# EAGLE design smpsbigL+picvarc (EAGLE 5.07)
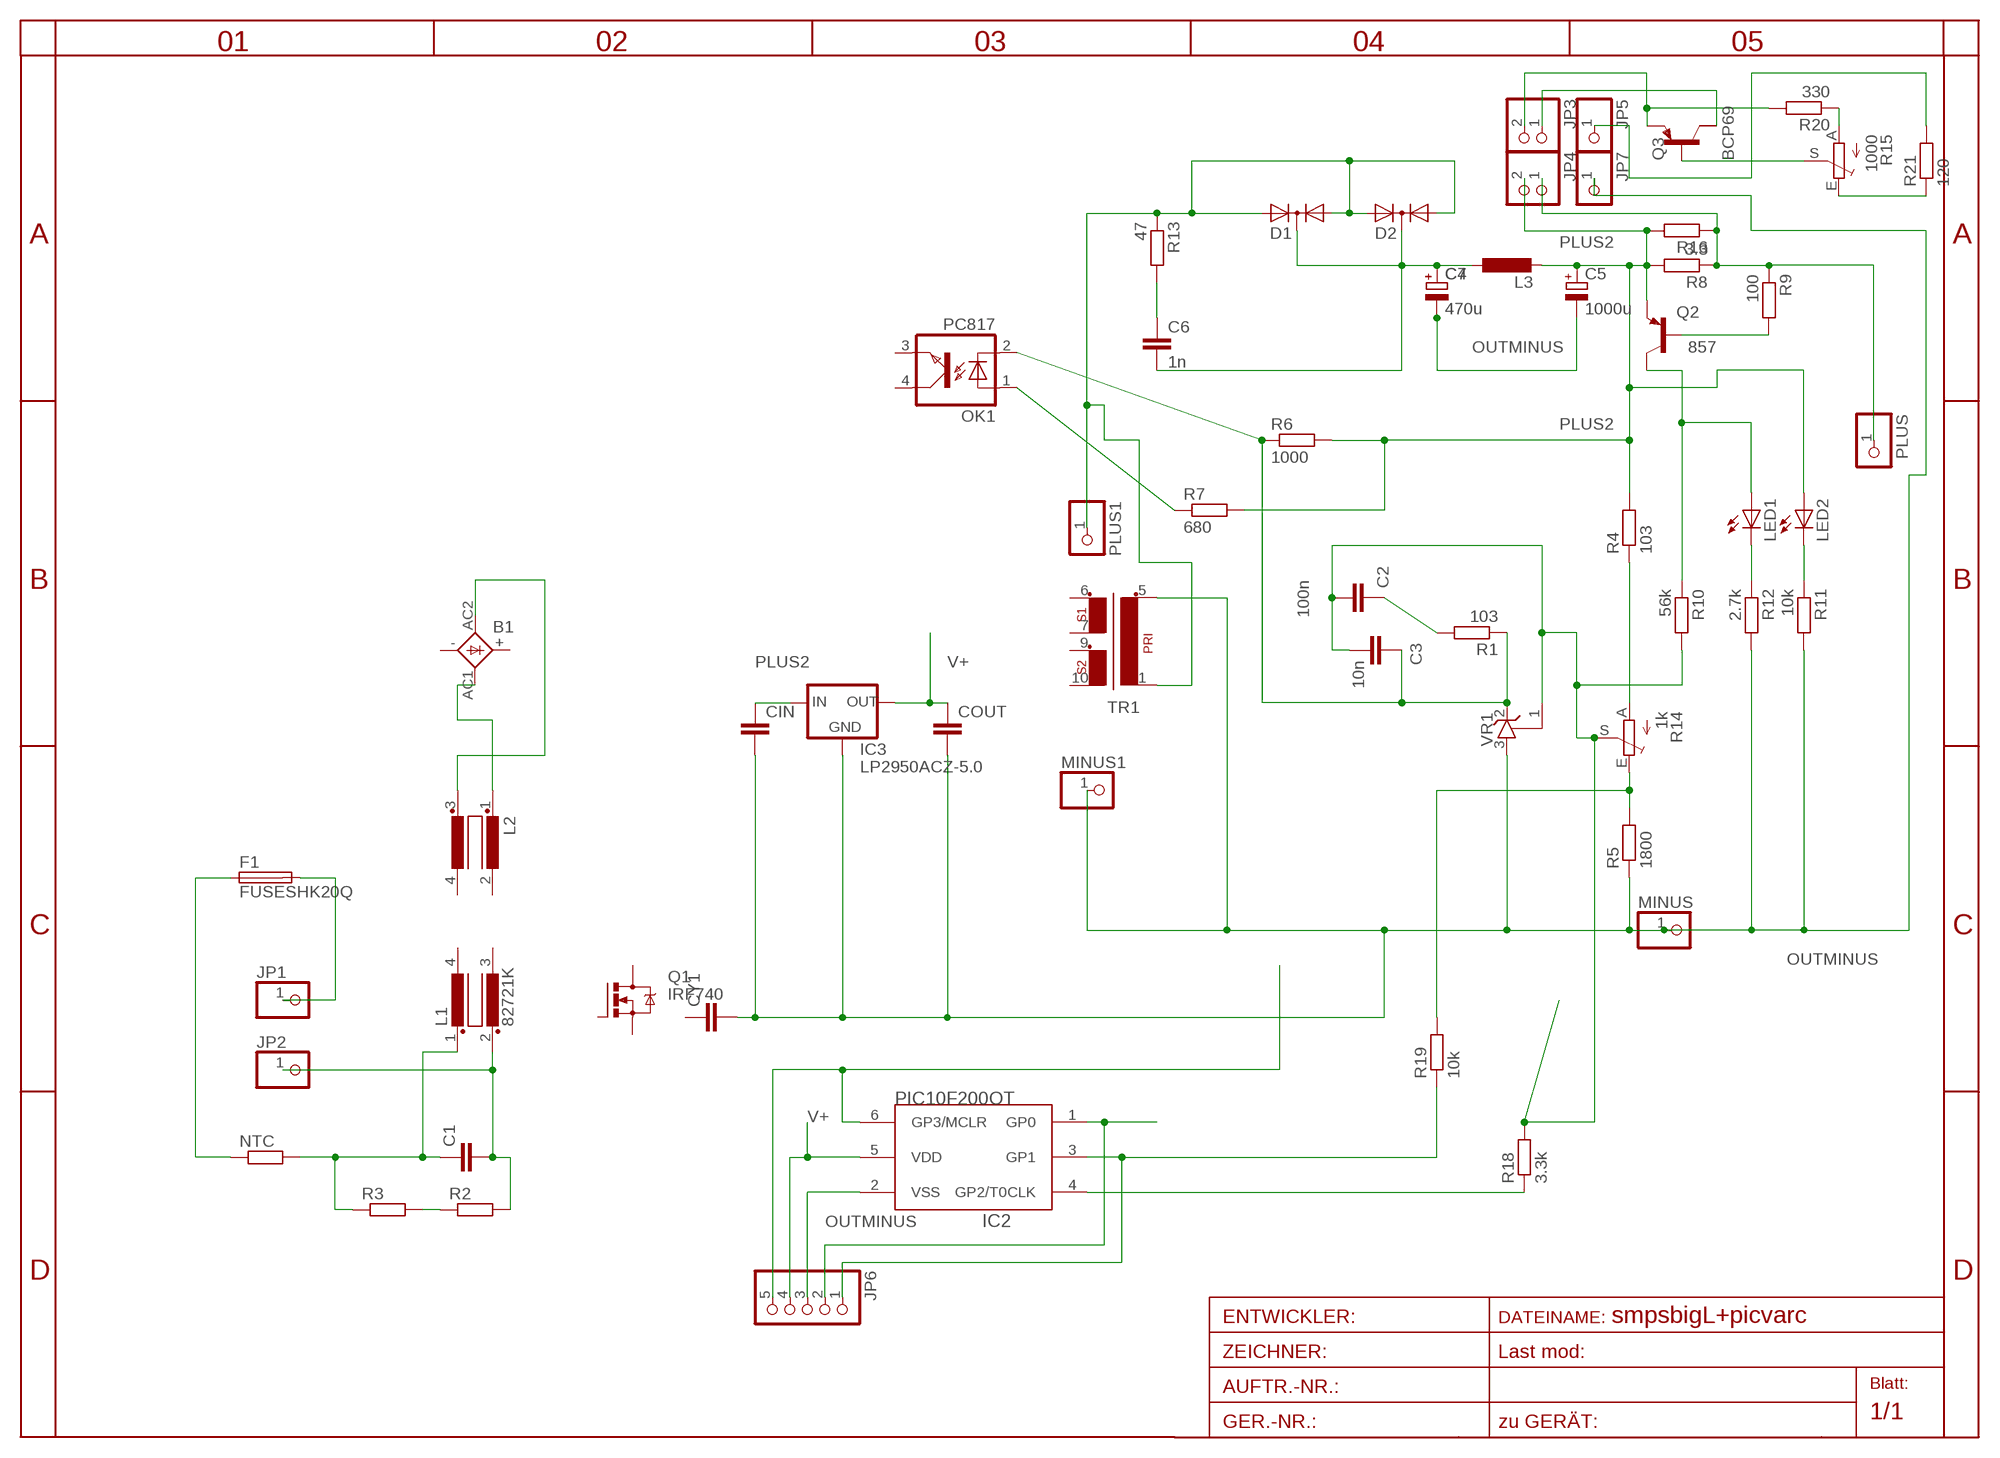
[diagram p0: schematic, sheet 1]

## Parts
B1  KBL  [KBL]
C1  C-EU150-084X183  [C150-084X183]
C2  100n  C-EUC0805  [C0805]
C3  10n  C-EUC0805  [C0805]
C4  CPOL-EUE5-8.5  [E5-8,5]
C5  1000u  CPOL-EUE5-8.5  [E5-8,5]
C6  1n  C-EUC0805  [C0805]
C7  470u  CPOL-EUE2.5-7  [E2,5-7]
CIN  C-EUC1206  [C1206]
COUT  C-EUC1206  [C1206]
CY1  C-EU075-063X106  [C075-063X106]
D1  DIODE-2AC|CAIW220V  [IW220ABS]
D2  DIODE-2AC|CAIW220V  [IW220ABS]
F1  FUSESHK20Q  [SHK20Q]
IC2  PIC10F200OT  [SOT23-6]
IC3  LP2950ACZ-5.0  [TO92]
JP1  PINHD-1X12MM2  [1X2MM2]
JP2  PINHD-1X12MM2  [1X2MM2]
JP3  PINHD-1X2STR  [1X02]
JP4  PINHD-1X2STR  [1X02]
JP5  PINHD-1X11X0.4  [1X01]
JP6  PINHD-1X5/90  [1X05/90]
JP7  PINHD-1X11X0.4  [1X01]
L1  82721K  [82721K]
L2  R1405VB1  [B1]
L3  L-EUOPEN6  [OPEN6_3]
LED1  LED3MM  [LED3MM]
LED2  LED3MM  [LED3MM]
MINUS  PINHD-1X12MM2  [1X2MM2]
MINUS1  PINHD-1X11X0.4  [1X01]
NTC  R-EU_0204/7  [0204/7]
OK1  PC817  [DIL04]
PLUS  PINHD-1X12MM2  [1X2MM2]
PLUS1  PINHD-1X11X0.4  [1X01]
Q1  IRF740  [TO220BV]
Q2  857  BC857ASMD  [SOT23-BEC]
Q3  BCP69  FZT753SMD  [SOT223]
R1  103  R-EU_R0805  [R0805]
R2  R-EU_R1206  [R1206]
R3  R-EU_R1206  [R1206]
R4  103  R-EU_R0805  [R0805]
R5  1800  R-EU_R0805  [R0805]
R6  1000  R-EU_R0805  [R0805]
R7  680  R-EU_R0805  [R0805]
R8  3.3  R-EU_R1210  [R1210]
R9  100  R-EU_0204/7  [0204/7]
R10  56k  R-EU_R0805  [R0805]
R11  10k  R-EU_R0805  [R0805]
R12  2.7k  R-EU_R0805  [R0805]
R13  47  R-EU_R1206  [R1206]
R14  1k  TRIM_EU-S64W  [S64W]
R15  1000  TRIM_EU-RAND160  [RANDL]
R16  R-EU_R2010  [R2010]
R18  3.3k  R-EU_R0805  [R0805]
R19  10k  R-EU_R0805  [R0805]
R20  330  R-EU_R0805  [R0805]
R21  120  R-EU_R0805  [R0805]
TR1  EE20-2  [EE30GREEN]
VR1  TL431CLPSOT23  [SOT23]

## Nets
A: R4.1 R14.A
C1: LED1.A Q2.C R10.1
CPLUS: C4.+ C6.2 C7.+ D1.C D2.C L3.1
E: R5.2 R14.E R19.2
N$1: C1.2 JP2.1 L1.2 R2.2
N$2: C1.1 L1.1 NTC.2 R3.1
N$3: F1.2A JP1.1
N$4: Q3.1(B) R15.S
N$5: R15.A R20.1
N$6: R2.1 R3.2
N$7: B1.AC2(AC1) L2.3
N$8: B1.AC1(AC2) L2.1
N$9: F1.1A NTC.1
N$10: R15.E R21.1
N$11: C3.1 OK1.2(C) R1.1 R6.1 VR1.2(C)
N$12: OK1.1(A) R7.1
N$13: C2.1 R1.2
N$14: JP3.2 Q3.3(E) R20.2
N$15: IC2.6(GP3/MCLR) JP6.5
N$16: Q2.B R9.2
N$17: IC2.1(GP0) JP6.2
N$18: IC2.3(GP1) JP6.1 R19.1
N$19: IC2.4(GP2/T0CLK) R18.1
N$20: JP3.1 Q3.2(C)
N$21: LED1.K(C) R12.1
N$22: JP5.1 R21.2
N$23: LED2.K(C) R11.1
N$27: C6.1 R13.2
OUTMINUS: C4.- C5.- C7.- CIN.2 COUT.2 CY1.2 IC2.2(VSS) IC3.2(GND) JP6.3 JP7.1 MINUS1.1 MINUS.1 R5.1 R11.2 R12.2 TR1.5 VR1.3(A)
OUTPLUS: JP4.1 PLUS.1 R8.1 R9.1 R16.1
PLUS2: C5.+ CIN.1 IC3.3(IN) JP4.2 L3.2 LED2.A Q2.E R4.2 R6.2 R7.2 R8.2 R16.2
S: C2.2 C3.2 R10.2 R14.S R18.2 VR1.1(R)
TOUT: D1.A1 D1.A2 D2.A1 D2.A2 PLUS1.1 R13.1 TR1.1
V+: COUT.1 IC2.5(VDD) IC3.1(OUT) JP6.4
Unconnected: B1.+ B1.- CY1.1 L1.3 L1.4 L2.2 L2.4 OK1.3(EMIT) OK1.4(COL) Q1.D Q1.G Q1.S Q3.4(C/) TR1.6 TR1.7 TR1.9 TR1.10

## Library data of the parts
B1 = rectifier:KBL: DIOTEC RECTIFIER
C1-C3 C6 CIN COUT CY1 = rcl:C-EU: CAPACITOR, European symbol
C4 C5 C7 = rcl:CPOL-EU: POLARIZED CAPACITOR, European symbol
D1 D2 = diode:DIODE-2AC|CA: Dual DIODE Anode-Cathode|Cathode-Anode
F1 = fuse:FUSE: Fuse
IC2 = microchip-5:PIC10F20*: uPC nW 0,25/0,5k Program Flash memory
IC3 = v-reg:LP2950?*: Source: http://cache.national.com/ds/LP/LP2950.pdf
JP1 JP2 JP5 JP7 MINUS MINUS1 PLUS PLUS1 = pinhead:PINHD-1X1: PIN HEADER
JP3 JP4 = pinhead:PINHD-1X2: PIN HEADER
JP6 = pinhead:PINHD-1X5: PIN HEADER
L1 = inductors:82721K: FILTER
L2 = inductor-nkl:R1405V: Übertrager (verlustarm) bis typ. 400kHz Power transformer (low loss) up to typ. 400kHz
L3 = rcl:L-EU: INDUCTOR, European symbol
LED1 LED2 = led:LED: LED
NTC R1-R13 R16 R18-R21 = rcl:R-EU_: RESISTOR, European symbol
OK1 = optocoupler:PC817: SHARP OPTO COUPLER
Q1 = transistor-power:IRF740: N-CHANNEL MOS FET
Q2 = transistor-pnp:BC857*: PNP Transistror
Q3 = transistor-pnp:FZT753SMD: PNP Transistor
R14 R15 = pot:TRIM_EU-: POTENTIOMETER
TR1 = trafo:EE20-2: TRANSFORMER 1 primary winding, 2 secondary windings ERA
VR1 = v-reg:TL431CLP: VOLTAGE REGULATOR

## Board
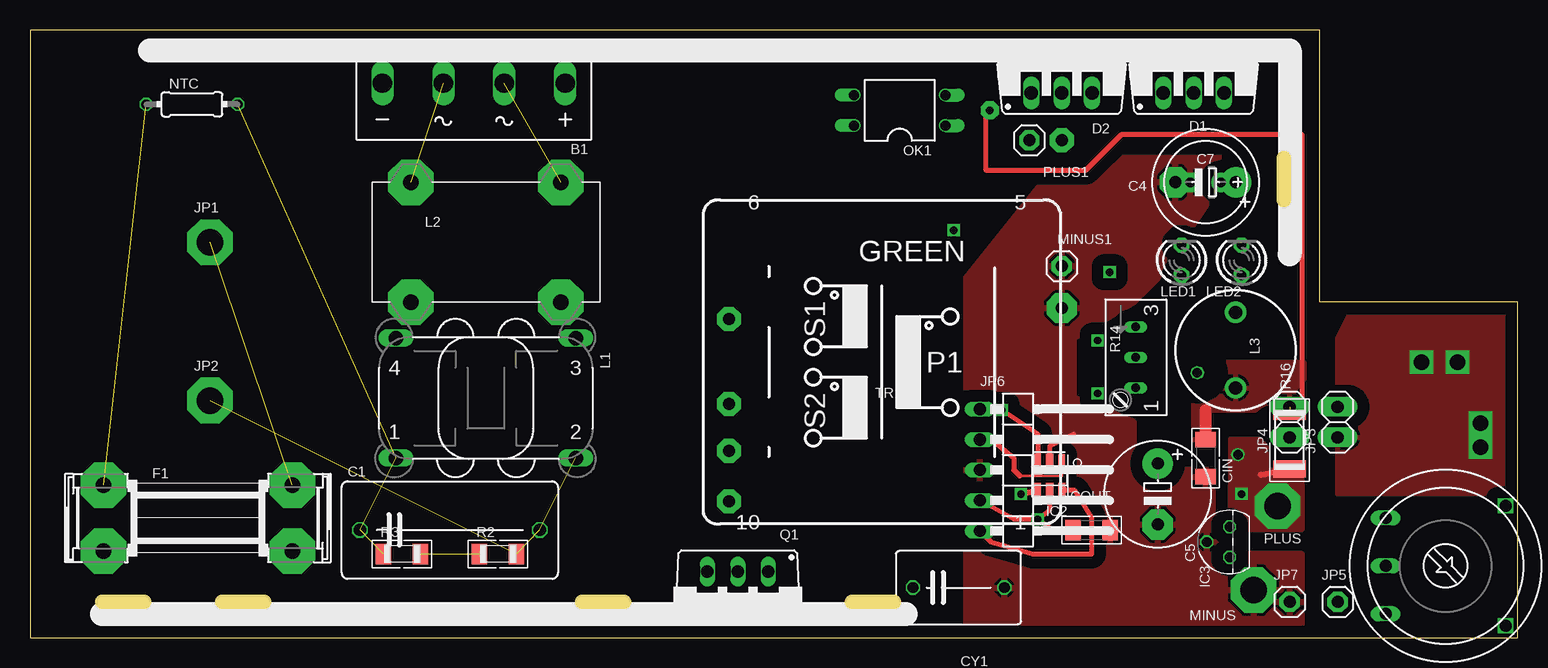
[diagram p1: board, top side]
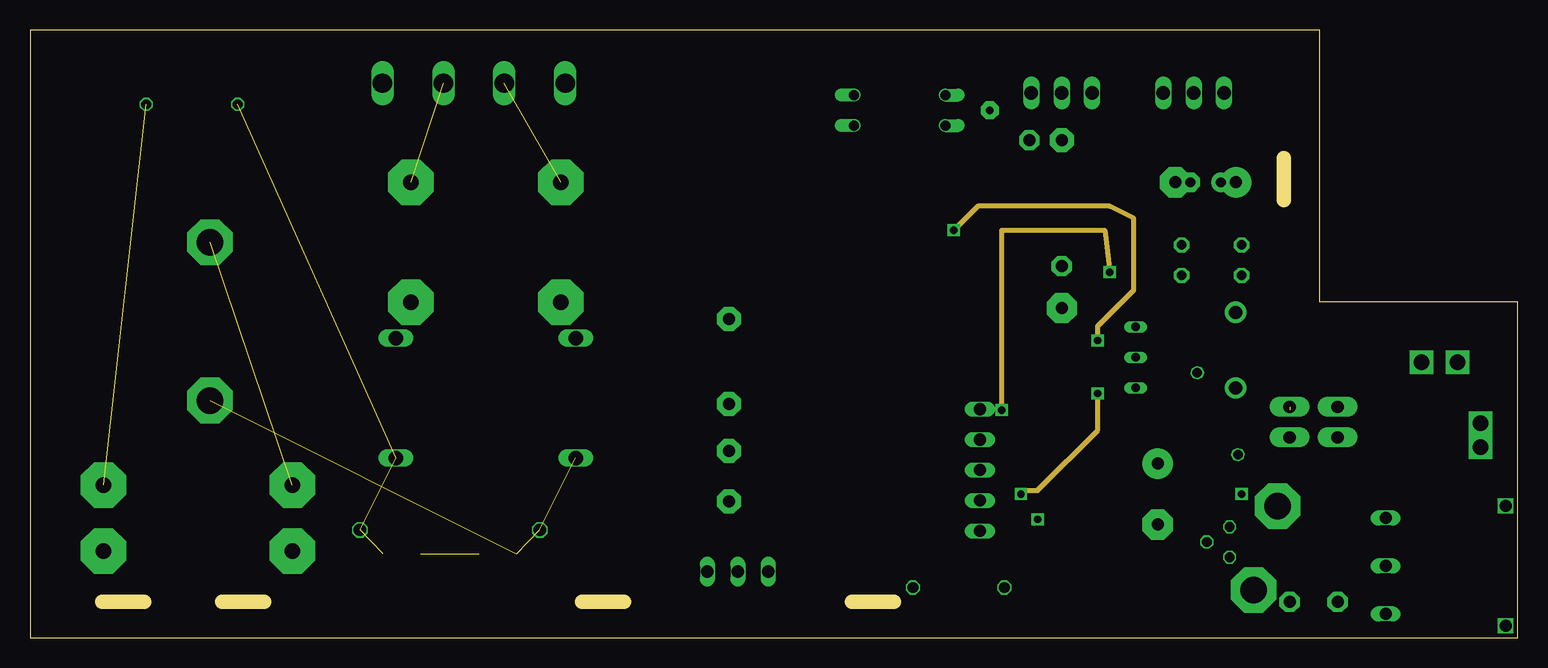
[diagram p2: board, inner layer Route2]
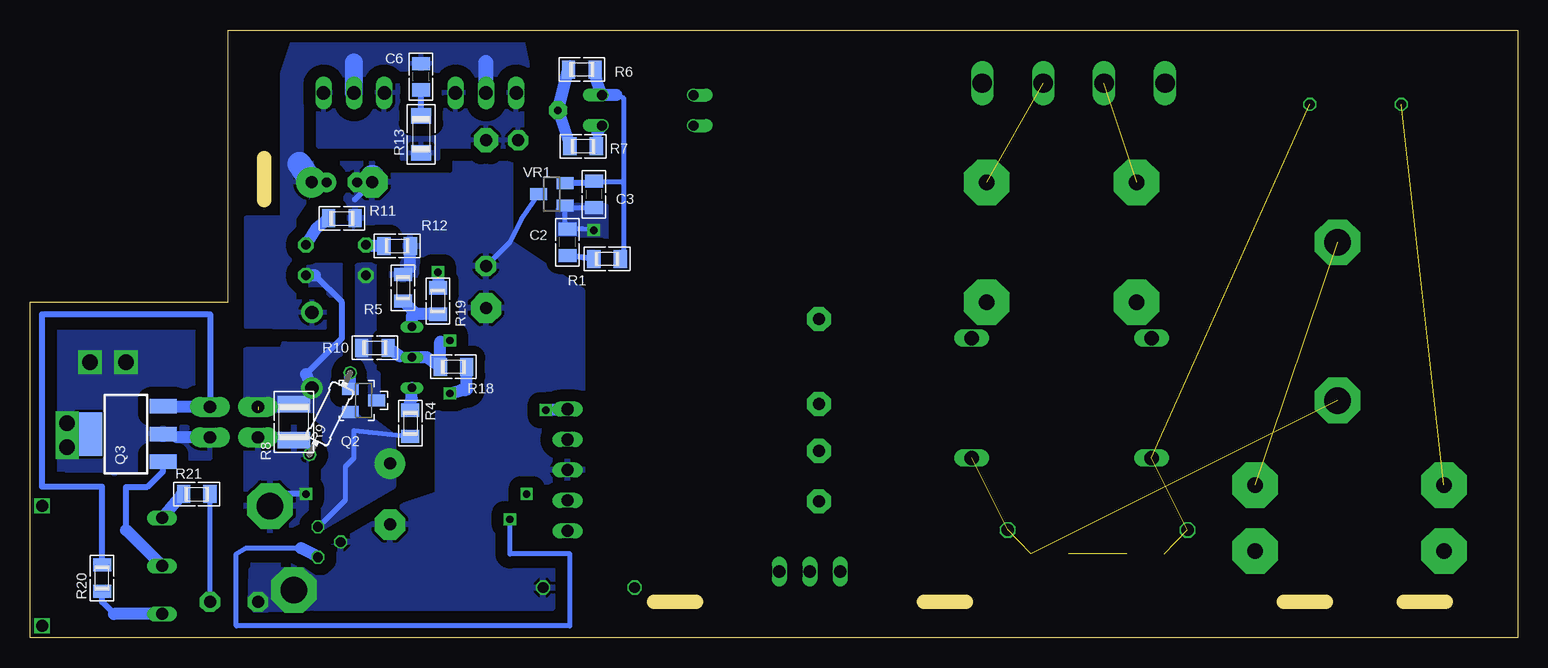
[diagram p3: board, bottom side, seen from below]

Size 124 x 50.7 mm. Coordinates in mm from the lower left corner, seen from the top.
Outline: 0,0 124,0 124,28 107.5,28 107.5,50.7 0,50.7 0,0
Copper layers (1*16): Top 0.035mm / dielectric 1.5mm / Bottom 0.035mm
Design rules "default *": minimum track width 10mil, minimum drill 20mil, track to track 8mil, track to pad 8mil, pad to pad 8mil, via to via 8mil, smd to smd 8mil, copper to edge 40mil, drill to drill 8mil, minimum pad ring 5mil, minimum via ring 8mil, stop-mask expansion 4mil, vias tented up to drill 0mil, thermal gap 10mil
Milling: 5 lines

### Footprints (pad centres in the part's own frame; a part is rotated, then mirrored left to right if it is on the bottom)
KBL = drill 1.6 long: + -7.62,-1.27; - 7.62,-1.27; AC1 2.54,-1.27; AC2 -2.54,-1.27
C150-084X183 = drill 1.016 octagon: 1 -7.493,0; 2 7.493,0
C0805 = smd 1.1 x 1.5: 1 -1.1,0; 2 1.1,0
E5-8,5 = drill 1 pad 2.54 round: + -2.54,0 | drill 1 pad 2.54 octagon: - 2.54,0
E2,5-7 = drill 0.813 pad 1.6 round: + -1.27,0 | drill 0.813 pad 1.6 octagon: - 1.27,0
C1206 = smd 1.3 x 1.7: 1 -1.55,0; 2 1.55,0
C075-063X106 = drill 0.914 octagon: 1 -3.81,0; 2 3.81,0
IW220ABS = drill 1.118 long: A1 -2.54,-2.54; A2 2.54,-2.54; C 0,-2.54
SHK20Q = drill 1.3 pad 3.81 octagon: 1A -7.874,2.75; 1B -7.874,-2.75; 2A 7.874,2.75; 2B 7.874,-2.75
SOT23-6 = smd 0.55 x 1.2: 1 -1.016,-1.2 | smd 0.6 x 1.27: 2 0,-1.2; 3 1.016,-1.2; 4 1.016,1.2; 5 0,1.2; 6 -1.016,1.2
TO92 = drill 0.813 octagon: 1 -1.27,0; 2 0,1.905; 3 1.27,0
1X2MM2 = drill 2.2 pad 3.81 octagon: 1 0,0
1X02 = drill 1.016 pad 1.676 long: 1 -1.27,0; 2 1.27,0
1X01 = drill 1 pad 1.676 octagon: 1 0,0
1X05/90 = drill 1.016 long: 1 -5.08,-3.81; 2 -2.54,-3.81; 3 0,-3.81; 4 2.54,-3.81; 5 5.08,-3.81
82721K = drill 1.194 long: 1 7.493,5.004; 2 -7.493,5.004; 3 -7.493,-5.004; 4 7.493,-5.004
B1 = drill 1.27 pad 3.81 octagon: 1 -6.25,5; 2 -6.25,-5; 3 6.25,5; 4 6.25,-5
OPEN6_3 = drill 1.1 pad 1.778 round: 1 -3.15,0; 2 3.15,0
LED3MM = drill 0.8 pad 1.27 octagon: A -1.27,0; K 1.27,0
0204/7 = drill 0.813 octagon: 1 -3.81,0; 2 3.81,0
DIL04 = drill 0.813 offset: 1 -1.27,-3.81; 2 1.27,-3.81; 3 1.27,3.81; 4 -1.27,3.81
TO220BV = drill 1.016 long: D 0,-2.54; G -2.54,-2.54; S 2.54,-2.54
SOT23-BEC = smd 1 x 1.4: B -0.95,-1.1; C 0,1.1; E 0.95,-1.1
SOT223 = smd 1.219 x 2.235: 1 -2.311,-3.099; 2 0,-3.099; 3 2.311,-3.099 | smd 3.6 x 2.2: 4 0,3.099
R0805 = smd 1.1 x 1.5: 1 -1.1,0; 2 1.1,0
R1206 = smd 1.3 x 1.7: 1 -1.55,0; 2 1.55,0
R1210 = smd 1.4 x 2.7: 1 -1.5,0; 2 1.5,0
S64W = drill 0.7 long: A 2.54,1.27; E -2.54,1.27; S 0,1.27
RANDL = drill 1 long: A -4,5; E 4,5; S 0,5 | drill 1 square: P$1 -5,-5; P$2 5,-5
R2010 = smd 1.4 x 2.7: 1 -2.4,0; 2 2.4,0
EE30GREEN = drill 1 pad 2 octagon: 1 15,18.5; 6 -12.75,3.6; 7 -12.75,-3.5; 9 -12.75,-7.4; 10 -12.75,-11.6 | drill 1 pad 2.5 octagon: 5 15,4.5
SOT23 = smd 1 x 1.4: 1 -0.95,-1.1; 2 0.95,-1.1; 3 0,1.1

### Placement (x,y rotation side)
B1  37,45 180 top
C1  35,9 0 top
C2  79.2,33 90 bottom
C3  77,37 270 bottom
C4  98,38 180 top
C5  94,12 270 top
C6  91.4,46.8 90 bottom
C7  98,38 180 top
CIN  98,15 270 top
COUT  88.5,9 0 top
CY1  77.4,4.2 0 top
D1  97,48 0 top
D2  86,48 0 top
F1  14,10 0 top
IC2  85,13.5 180 top
IC3  100,8 90 top
JP1  15,33 0 top
JP2  15,19.8 0 top
JP3  109,18 90 top
JP4  105,18 90 top
JP5  109,3 0 top
JP6  83,14 270 top
JP7  105,3 0 top
L1  38,20 180 top
L2  38,33 0 top
L3  100.5,24 270 top
LED1  96,31.5 90 top
LED2  101,31.5 90 top
MINUS  102,4 0 top
MINUS1  86,31 0 top
NTC  13.5,44.5 0 top
OK1  72.5,44 90 top
PLUS  104,11 0 top
PLUS1  83.3,41.5 0 top
Q1  59,3 180 top
Q2  96.2,19.8 270 bottom
Q3  116,17 90 bottom
R1  75.9,31.6 180 bottom
R2  39,7 0 top
R3  31,7 0 top
R4  92.3,17.9 270 bottom
R5  92.9,29.2 270 bottom
R6  78,47.4 180 bottom
R7  77.9,41 180 bottom
R8  102,18 90 bottom
R9  99,18.7 63.5 bottom
R10  95.25,24.2 0 bottom
R11  98,35 0 bottom
R12  93.4,32.7 0 bottom
R13  91.4,42 90 bottom
R14  90.9,23.4 270 top
R15  118,6 90 top
R16  105,16.5 90 top
R18  88.7,22.6 180 bottom
R19  90,28.1 270 bottom
R20  118,5 90 bottom
R21  110.1,12 0 bottom
TR1  71,23 0 top
VR1  80.5,37 90 bottom

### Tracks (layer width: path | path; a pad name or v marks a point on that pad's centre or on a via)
A
  Bottom 0.406: 92.3,19.7 92.17,19.93
  Bottom 1.016: R4.1 92.3,19.7 | 92.17,19.93 R14.A
C1
  pour Bottom (isolate 0.8, rank 3, no thermals): 95.3,31.2 96.7,31 96.7,19.9 95,20 95,22 95.3,22.2
CPLUS
  Bottom 1.27: D2.C 86,48
  Bottom 1.5: D1.C 97,48
  Bottom 2: C4.+ 101.54,39.54
  pour Bottom (isolate 1, rank 3): 83,50 102,50 103,47 103,35 106,35 106,26 99.4,25.9 99.4,28 102,28 102,31 102,35 100,38 101.1,45.8 82.1,45.8
E
  Bottom 0.406: 91.8,27 91.9,27.1 92.17,26.83
  Bottom 1.016: R19.2 91.8,27 | 91.9,27.1 R5.2 | 92.17,26.83 R14.E
N$1  (3 unrouted)
N$2  (3 unrouted)
N$3  (1 unrouted)
N$4
  Bottom 0.5: 116,9 116,12.59 114.2,12.6 112.9,13.9 Q3.1
  Bottom 1: R15.S 116,9
N$5
  Bottom 0.5: 117,2 118,3 R20.1
  Bottom 1: R15.A 117,2
N$6  (1 unrouted)
N$7  (1 unrouted)
N$8  (1 unrouted)
N$9  (1 unrouted)
N$10
  Bottom 0.406: R21.1 111.4,11.9
  Bottom 1: 111.4,11.9 R15.E
N$11
  Bottom 0.406: 77.15,37.95 C3.1 76.9,38 74.5,38 | 74.5,31.8 74.5,38 | 76.81,46.61 R6.1 | 75.13,45.27 74.5,45 74.5,38
  Bottom 0.5: 77.15,37.95 VR1.2 | R1.1 74.5,31.8
  Bottom 1: 76.81,46.61 OK1.2 75.13,45.27
N$12
  Bottom 0.5: R7.1 76.7,42.14
  Bottom 1: 76.7,42.14 OK1.1
N$13
  Bottom 0.5: R1.2 C2.1
N$14
  Bottom 0.406: 112.86,19.27 Q3.3
  Bottom 0.5: R20.2 118,12.6 123,12.6 123,27 109,27 JP3.2
  Bottom 1.016: JP3.2 112.86,19.27
N$15
  Top 0.406: IC2.6 87.1,12.3 88.5,10 88.5,7 83.6,7 80.11,8 JP6.5
N$16
  Bottom 1.016: Q2.B R9.2
N$17
  Top 0.2: IC2.1 86.02,13.52 86,13.5 82.5,13.5
  Top 0.406: 82.5,13.5 82,14 82,15 80.1,16.6 79.75,16.6 JP6.2
N$18  (via drill 0.6)
  Top 0.406: JP6.1 81.08,19.08 | IC2.3 84,14.72 84,17 v81,19
  Route2 0.406: v81,19 81,34 89.6,34 v90,30.5
  Bottom 1.016: v90,30.5 R19.1 | v81,19 79.27,19 JP6.1
N$19  (via drill 0.6)
  Top 0.5: v82.6,12 IC2.4
  Route2 0.406: v89,20.4 89,17.32 IC2.4 82.9,12.3 v82.6,12
  Bottom 1: 87.6,20.7 88,20.7 v89,20.4
  Bottom 1.016: 87.6,20.7 R18.1
N$20  (via drill 0.6, 1.3 pad 1.5)
  Bottom 0.406: 111.73,16.73 112,17 Q3.2
  Bottom 1.016: JP3.1 111.73,16.73
  other vias: 119,23 119,23 116,23 120.9,17.9 120.9,15.9
  pour Bottom (isolate 1): 110,26 122,26 122,10 115,10 111,13 111,15 109,15 109,25
  pour Top (isolate 1): 110,27 123,27 123,12 109,12 109,25
  pour Bottom (no thermals): 117,20 121,20 121,14 117,14
N$21
  Bottom 1.016: R12.1 95.93,32.7 LED1.K
N$22
  Bottom 0.406: JP5.1 R21.2
N$23
  Bottom 1: LED2.K 100.1,34.2
  Bottom 1.016: 100.1,34.2 R11.1
N$27
  Bottom 0.5: R13.2 C6.1
OUTMINUS
  Top 0.4: IC2.2 85,16 87,17
  Bottom 0.406: VR1.3 83,35 84,33 MINUS1.1 | R5.1 92.3,30.9
  Bottom 0.5: C4.- 96.9,36.56
  Bottom 1.016: 92.3,30.9 R12.2
  Bottom 2: C4.- 95.46,38.46
  pour Bottom (isolate 1, rank 5): 98,40 84,40 84,33 78,29 78,5 82,1 106,1 107,2 107,6 106,7 99,7 99,9 90,12 90,28 96,28 98,36
  pour Top (isolate 1, rank 5): 100,40 86,40 78,30 78,0 106,0 106,7 101,7 101,14 92,14 92,18 87,20 87,25 92,28 94,30 98,36
  pour Bottom (no thermals): 105.7,2.8 105.3,2.3 99.5,2.5 99.5,5 100.2,5 101.2,5.7 105.6,5.7
OUTPLUS  (via drill 0.6)
  Top 0.5: 102.6,13.6 R16.1
  Bottom 0.5: v101,12 102.6,12 PLUS.1
  pour Bottom (isolate 1): 106,18 106,9 103,9 101,10 101,18
  pour Top (isolate 1, no thermals): 100.1,16.6 102.4,16.6 103,16 103,14 106,14 106,9 100,9
PLUS2  (via drill 0.6 pad 1.5)  (1 unrouted)
  Top 0.406: R16.2 105,19 106,20 106,42 91,42 88,39 79.7,39 79.7,43.5 v80,44
  Top 1: CIN.1 98,19
  Bottom 0.4: IC3.3 99.93,9.27 97.7,11.5 97.7,14.3 97,15 97,17.3 R4.2
  Bottom 0.406: R6.2 79.2,47.2 79,48
  Bottom 0.5: 100.23,30.23 98,28 98,25 101,22
  Bottom 1: R7.2 v80,44 79.2,47.2 | 100.23,30.23 LED2.A | L3.2 101,22
  pour Bottom (isolate 1, rank 4, no thermals): 103,24 106,24 106,19 100,19 100,9 93.7,12.7 93.7,16.8 98,20 98,31 100.7,31
  pour Top (isolate 2, rank 2): 98,23 106.2,23 106.2,19 105,18 97,16 97,22
S  (via drill 0.6)
  Route2 0.406: v89,24.8 89.2,24.8 89,25 89,26 92,29 92,35 90,36 79,36 v77,34
  Bottom 0.406: C3.2 79.25,35.9 VR1.1 79.4,34.3 C2.2 77.9,34.1 v77,34 | R18.2 89.8,22.9 | 89.8,24.7 v89,24.8 | R14.S 93.17,23.5
  Bottom 1.016: 89.8,22.9 89.8,24.7 | 93.17,23.5 R10.2 | R14.S 90.9,23.4 R18.2
  pour Bottom (isolate 1, rank 3, no thermals): 76,36 80,36 80,33 76,33
TOUT
  pour Bottom (isolate 1, rank 2): 83,46 100,46 100,41 93,41 93,40 90,40 90,41 83,41
V+  (via drill 0.6)
  Top 0.4: v84,9.9 85.25,9 COUT.1
  Top 0.406: IC2.5 85,10.7 84.8,10.5 v84,9.9 82,9.9 81.74,10.06 JP6.4
  Bottom 0.406: 101.4,7.5 106,7.5 106.8,7 106.8,1 79,1 79,7 84,7 v84,9.9
  Bottom 1: IC3.1 100.4,7 101.4,7.5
